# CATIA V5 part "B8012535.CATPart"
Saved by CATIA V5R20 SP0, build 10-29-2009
Part number: B8012535
Revision: 8
Definition: design
Nomenclature: B8012535
Source: made
Description: NOT SPECIFIED
Bounding box of the stored display mesh (mm): x -22.5 to 22.5, y -22.5 to 22.5, z 0 to 35
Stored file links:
  C:\Users\Utente\Desktop\3D files B801\B8012535.CATPart
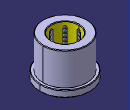
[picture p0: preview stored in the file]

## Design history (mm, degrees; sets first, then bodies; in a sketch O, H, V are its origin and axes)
Body1 "MANIFOLD_SOLID_BREP #38" (main body)
  Solid1: solid without history
Body2 "MANIFOLD_SOLID_BREP #76"
  Solid2: solid without history
Body3 "MANIFOLD_SOLID_BREP #114"
  Solid3: solid without history
Body4 "MANIFOLD_SOLID_BREP #152"
  Solid4: solid without history
Body5 "MANIFOLD_SOLID_BREP #190"
  Solid5: solid without history
Body6 "MANIFOLD_SOLID_BREP #228"
  Solid6: solid without history
Body7 "MANIFOLD_SOLID_BREP #266"
  Solid7: solid without history
Body8 "MANIFOLD_SOLID_BREP #304"
  Solid8: solid without history
Body9 "MANIFOLD_SOLID_BREP #342"
  Solid9: solid without history
Body10 "MANIFOLD_SOLID_BREP #2272"
  Solid10: solid without history
Body11 "MANIFOLD_SOLID_BREP #2310"
  Solid11: solid without history
Body12 "MANIFOLD_SOLID_BREP #2348"
  Solid12: solid without history
Body13 "MANIFOLD_SOLID_BREP #2386"
  Solid13: solid without history
Body14 "MANIFOLD_SOLID_BREP #2424"
  Solid14: solid without history
Body15 "MANIFOLD_SOLID_BREP #2462"
  Solid15: solid without history
Body16 "MANIFOLD_SOLID_BREP #2500"
  Solid16: solid without history
Body17 "MANIFOLD_SOLID_BREP #2538"
  Solid17: solid without history
Body18 "MANIFOLD_SOLID_BREP #2576"
  Solid18: solid without history
Body19 "MANIFOLD_SOLID_BREP #2614"
  Solid19: solid without history
Body20 "MANIFOLD_SOLID_BREP #2652"
  Solid20: solid without history
Body21 "MANIFOLD_SOLID_BREP #2690"
  Solid21: solid without history
Body22 "MANIFOLD_SOLID_BREP #2728"
  Solid22: solid without history
Body23 "MANIFOLD_SOLID_BREP #2766"
  Solid23: solid without history
Body24 "MANIFOLD_SOLID_BREP #2804"
  Solid24: solid without history
Body25 "MANIFOLD_SOLID_BREP #2842"
  Solid25: solid without history
Body26 "MANIFOLD_SOLID_BREP #2880"
  Solid26: solid without history
Body27 "MANIFOLD_SOLID_BREP #2918"
  Solid27: solid without history
Body28 "MANIFOLD_SOLID_BREP #2956"
  Solid28: solid without history
Body29 "MANIFOLD_SOLID_BREP #2994"
  Solid29: solid without history
Body30 "MANIFOLD_SOLID_BREP #3032"
  Solid30: solid without history
Body31 "MANIFOLD_SOLID_BREP #3070"
  Solid31: solid without history
Body32 "MANIFOLD_SOLID_BREP #3108"
  Solid32: solid without history
Body33 "MANIFOLD_SOLID_BREP #3146"
  Solid33: solid without history
Body34 "MANIFOLD_SOLID_BREP #3184"
  Solid34: solid without history
Body35 "MANIFOLD_SOLID_BREP #3222"
  Solid35: solid without history
Body36 "MANIFOLD_SOLID_BREP #3260"
  Solid36: solid without history
Body37 "MANIFOLD_SOLID_BREP #3298"
  Solid37: solid without history
Body38 "MANIFOLD_SOLID_BREP #3336"
  Solid38: solid without history
Body39 "MANIFOLD_SOLID_BREP #3374"
  Solid39: solid without history
Body40 "MANIFOLD_SOLID_BREP #3412"
  Solid40: solid without history
Body41 "MANIFOLD_SOLID_BREP #3450"
  Solid41: solid without history
Body42 "MANIFOLD_SOLID_BREP #3488"
  Solid42: solid without history
Body43 "MANIFOLD_SOLID_BREP #3526"
  Solid43: solid without history
Body44 "MANIFOLD_SOLID_BREP #3564"
  Solid44: solid without history
Body45 "MANIFOLD_SOLID_BREP #3602"
  Solid45: solid without history
Body46 "MANIFOLD_SOLID_BREP #3640"
  Solid46: solid without history
Body47 "MANIFOLD_SOLID_BREP #3678"
  Solid47: solid without history
Body48 "MANIFOLD_SOLID_BREP #3716"
  Solid48: solid without history
Body49 "MANIFOLD_SOLID_BREP #3754"
  Solid49: solid without history
Body50 "MANIFOLD_SOLID_BREP #3792"
  Solid50: solid without history
Body51 "MANIFOLD_SOLID_BREP #3830"
  Solid51: solid without history
Body52 "MANIFOLD_SOLID_BREP #3868"
  Solid52: solid without history
Body53 "MANIFOLD_SOLID_BREP #3906"
  Solid53: solid without history
Body54 "MANIFOLD_SOLID_BREP #3944"
  Solid54: solid without history
Body55 "MANIFOLD_SOLID_BREP #3982"
  Solid55: solid without history
Body56 "MANIFOLD_SOLID_BREP #4020"
  Solid56: solid without history
Body57 "MANIFOLD_SOLID_BREP #4058"
  Solid57: solid without history
Body58 "MANIFOLD_SOLID_BREP #4096"
  Solid58: solid without history
Body59 "MANIFOLD_SOLID_BREP #4134"
  Solid59: solid without history
Body60 "MANIFOLD_SOLID_BREP #4172"
  Solid60: solid without history
Body61 "MANIFOLD_SOLID_BREP #4210"
  Solid61: solid without history
Body62 "MANIFOLD_SOLID_BREP #4248"
  Solid62: solid without history
Body63 "MANIFOLD_SOLID_BREP #4286"
  Solid63: solid without history
Body64 "MANIFOLD_SOLID_BREP #4324"
  Solid64: solid without history
Body65 "MANIFOLD_SOLID_BREP #4362"
  Solid65: solid without history
Body66 "MANIFOLD_SOLID_BREP #4400"
  Solid66: solid without history
Body67 "MANIFOLD_SOLID_BREP #4438"
  Solid67: solid without history
Body68 "MANIFOLD_SOLID_BREP #4476"
  Solid68: solid without history
Body69 "MANIFOLD_SOLID_BREP #4514"
  Solid69: solid without history
Body70 "MANIFOLD_SOLID_BREP #4552"
  Solid70: solid without history
Body71 "MANIFOLD_SOLID_BREP #4590"
  Solid71: solid without history
Body72 "MANIFOLD_SOLID_BREP #4628"
  Solid72: solid without history
Body73 "MANIFOLD_SOLID_BREP #4666"
  Solid73: solid without history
